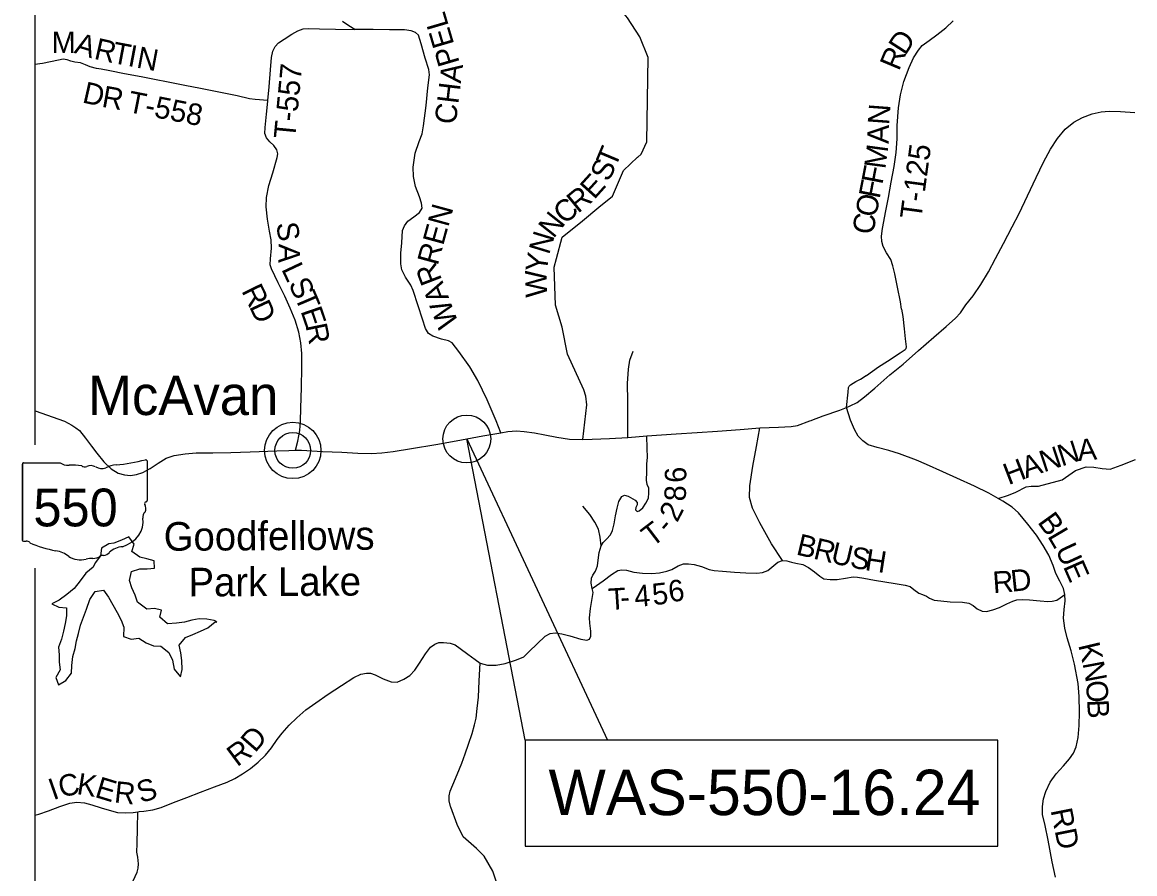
# Model space of a CAD drawing. Extents: x -84548 to 2262448, y -162180 to 525962.
# Drawn here: x 76911 to 92440, y 147226 to 159110 of the extents above; entities that cross this region are included whole.
import ezdxf

# ---------------------------------------------------------------- set-up
doc = ezdxf.new("R2010")
doc.units = 0
for name, color, linetype in [('GM_X_Adjacent_County_Text', 7, 'Continuous'), ('GM_X_County', 7, 'Continuous'), ('GM_X_County_Road', 7, 'Continuous'), ('GM_X_Interchange_Ramps', 7, 'Continuous'), ('GM_X_Major_Lake_Text', 7, 'Continuous'), ('GM_X_Major_River', 7, 'Continuous'), ('GM_X_Minor_Lake', 7, 'Continuous'), ('GM_X_Minor_River_Text', 7, 'Continuous'), ('GM_X_Rail_Line', 7, 'Continuous'), ('GM_X_Section', 7, 'Continuous'), ('GM_X_Township_Road', 7, 'Continuous'), ('GM_X_Township_Road_Text', 7, 'Continuous'), ('GM_X_Township_ROW', 7, 'Continuous'), ('GM_X_Unincorporated_Text', 7, 'Continuous')]:
    doc.layers.add(name, color=color, linetype=linetype)

msp = doc.modelspace()

# ---------------------------------------------------------------- linework, layer by layer
at = {"layer": 'GM_X_Adjacent_County_Text'}
msp.add_circle((83116, 153294), 334, dxfattribs=at)
at = {"layer": 'GM_X_County'}
for p, q in [((77085, 170686), (77085, 153214)), ((77085, 151493), (77085, 134782))]:
    msp.add_line(p, q, dxfattribs=at)
at = {"layer": 'GM_X_Interchange_Ramps'}
for points in [[(79613, 150749), (79589, 150761), (79487, 150779), (79382, 150783), (79276, 150765), (79175, 150735), (79065, 150723), (78938, 150713), (78831, 150805), (78855, 150906), (78755, 150926), (78650, 150920), (78520, 151014), (78488, 151114), (78441, 151216), (78407, 151317), (78437, 151445), (78552, 151483), (78656, 151483), (78757, 151489), (78751, 151591), (78650, 151619), (78550, 151643), (78439, 151724), (78473, 151826), (78399, 151926), (78294, 151882), (78190, 151842)], [(78190, 151842), (78118, 151832), (78017, 151772), (78005, 151665), (77929, 151563)], [(77929, 151563), (77901, 151507), (77800, 151421), (77720, 151313), (77637, 151208), (77533, 151124), (77428, 151046), (77322, 150992), (77422, 150946), (77527, 150938), (77529, 150827), (77511, 150717), (77488, 150613), (77460, 150499), (77416, 150388), (77426, 150282), (77424, 150178), (77442, 150074), (77378, 149963), (77416, 149861), (77517, 149925), (77597, 150026), (77601, 150130), (77615, 150258), (77649, 150370), (77669, 150477), (77696, 150581), (77726, 150697), (77768, 150809), (77806, 150920), (77854, 151052), (77929, 151164), (78047, 151184), (78114, 151084), (78174, 150978), (78236, 150874), (78291, 150765), (78331, 150665), (78325, 150535), (78429, 150499), (78538, 150515), (78640, 150449), (78741, 150409), (78847, 150403), (78956, 150312), (79008, 150206), (79032, 150082), (79119, 149976), (79141, 150076), (79137, 150200), (79123, 150308), (79101, 150417), (79189, 150523), (79290, 150565), (79398, 150611), (79499, 150657), (79605, 150741)], [(79605, 150741), (79629, 150737)], [(79629, 150737), (79613, 150749)]]:
    msp.add_lwpolyline(points, dxfattribs=at)
at = {"layer": 'GM_X_Major_Lake_Text'}
for points in [[(88418, 153735), (88468, 153756), (88567, 153804), (88669, 153883), (88810, 154002), (89021, 154188), (89205, 154337), (89422, 154529), (89633, 154715), (89806, 154862), (89937, 154981), (90006, 155055), (90083, 155166), (90183, 155293), (90293, 155450), (90398, 155629), (90495, 155812), (90610, 156023), (90730, 156254), (90825, 156443), (90945, 156688), (91065, 156943), (91164, 157158), (91263, 157341), (91360, 157488), (91467, 157617), (91588, 157716), (91709, 157783), (91845, 157832), (91971, 157861), (92085, 157869), (92241, 157866), (92441, 157852)], [(77085, 153691), (77093, 153688), (77501, 153542), (77602, 153487), (77658, 153449), (77712, 153411), (77795, 153303)], [(87925, 153553), (87930, 153555), (88089, 153617), (88324, 153697), (88418, 153735)], [(80465, 153129), (80633, 153135), (80724, 153137), (80807, 153138), (81101, 153120), (81371, 153108), (81593, 153097), (81787, 153092), (81931, 153099), (82090, 153118), (82346, 153160), (82685, 153216), (82969, 153266), (83342, 153337), (83592, 153380), (83691, 153397), (83811, 153406), (83917, 153398), (84059, 153379), (84207, 153352), (84373, 153319), (84549, 153292), (84737, 153288), (84865, 153292), (85107, 153300), (85365, 153316), (85628, 153338), (86038, 153366), (86332, 153383), (86615, 153405), (86931, 153427), (87207, 153448), (87468, 153461), (87644, 153466), (87732, 153480), (87905, 153546), (87925, 153553)], [(77795, 153303), (77879, 153192), (77953, 153098), (78050, 152976), (78153, 152879), (78249, 152819), (78337, 152792), (78423, 152786), (78505, 152797), (78595, 152826), (78694, 152882), (78808, 152955), (78919, 153026), (79031, 153063), (79185, 153086), (79340, 153099), (79572, 153102), (79822, 153106), (80090, 153116), (80465, 153129)]]:
    msp.add_lwpolyline(points, dxfattribs=at)
at = {"layer": 'GM_X_Major_River'}
for radius in [393, 249]:
    msp.add_circle((80687, 153134), radius, dxfattribs=at)
at = {"layer": 'GM_X_Minor_Lake'}
for points in [[(85502, 157226), (85551, 157270), (85627, 157441), (85646, 158620), (85531, 158905), (85360, 159171), (85265, 159285), (85208, 159343), (85170, 159419), (85208, 159514), (85170, 159666), (85056, 159856), (85075, 160521), (85126, 161488), (85126, 161489)], [(80437, 158763), (80441, 158771), (80488, 158824), (80565, 158874), (80672, 158942), (80759, 158992), (80834, 159017), (80904, 159023), (81062, 159020), (81284, 159016), (81552, 159010)], [(89187, 155106), (89186, 155107), (89168, 155210), (89127, 155413), (89092, 155597), (89063, 155711), (89035, 155797), (88976, 155891), (88926, 155981), (88909, 156049), (88903, 156123), (88918, 156233), (88965, 156476), (89002, 156666), (89039, 156877), (89082, 157097), (89109, 157294), (89122, 157484), (89125, 157671), (89141, 157917), (89170, 158097), (89215, 158282), (89290, 158481), (89352, 158615), (89419, 158720), (89473, 158788), (89568, 158857), (89678, 158935), (89801, 159032), (89905, 159131)], [(80724, 153137), (80758, 153262), (80785, 153413), (80796, 153544), (80800, 153726), (80808, 154013), (80815, 154293), (80813, 154489), (80800, 154637), (80773, 154783), (80721, 154952), (80652, 155121), (80576, 155288), (80485, 155471), (80391, 155667), (80370, 155723), (80378, 155807), (80391, 155955), (80384, 156074), (80362, 156195), (80335, 156361), (80315, 156535), (80318, 156663), (80355, 156830), (80407, 157009), (80471, 157223), (80478, 157275), (80463, 157331), (80423, 157392), (80368, 157443), (80319, 157498), (80298, 157558), (80300, 157640), (80321, 157829), (80339, 158010), (80340, 158019), (80357, 158208), (80378, 158445), (80392, 158618), (80409, 158706), (80437, 158762), (80437, 158763)], [(78010, 158455), (77980, 158460), (77945, 158467), (77860, 158489), (77794, 158518), (77723, 158542), (77643, 158551), (77589, 158568), (77536, 158587), (77484, 158596), (77415, 158580), (77192, 158534), (77085, 158520)], [(80340, 158019), (80163, 158032), (80084, 158043), (79912, 158081), (79633, 158138), (79398, 158185), (79181, 158229), (78948, 158276), (78757, 158313), (78569, 158349), (78340, 158392), (78133, 158432), (78010, 158455)], [(84367, 155812), (84367, 155814), (84448, 156111), (84733, 156339), (84961, 156529), (85151, 156681), (85208, 156814), (85303, 157042), (85501, 157225), (85502, 157226)], [(84737, 153288), (84790, 153772), (84778, 153892), (84752, 153982), (84524, 154476), (84448, 154856), (84353, 155160), (84334, 155693), (84367, 155812)], [(88695, 154182), (88865, 154300), (88990, 154378), (89165, 154497), (89233, 154544), (89249, 154559), (89253, 154578), (89242, 154690), (89226, 154832), (89205, 155004), (89187, 155106)], [(88418, 153735), (88441, 153945), (88446, 154011), (88455, 154032), (88470, 154049), (88546, 154098), (88612, 154130), (88693, 154181), (88695, 154182)], [(84868, 151209), (84850, 151281), (84859, 151351), (84876, 151393), (84913, 151448), (84941, 151523), (84952, 151601), (84966, 151710), (84991, 151801), (85019, 151851), (85068, 151894), (85122, 151955), (85151, 152018), (85173, 152110), (85193, 152219), (85213, 152330), (85237, 152420), (85279, 152489), (85317, 152510), (85367, 152497), (85466, 152441), (85493, 152407), (85494, 152377), (85474, 152339), (85473, 152303), (85492, 152283), (85523, 152290), (85573, 152333), (85617, 152396), (85652, 152470), (85658, 152541), (85657, 152607), (85636, 152660), (85625, 152718), (85628, 152833), (85630, 152943), (85640, 153039), (85636, 153161), (85628, 153338)], [(90535, 152462), (90679, 152508), (90782, 152550), (90925, 152625), (90993, 152637), (91097, 152633), (91426, 152724), (91614, 152854), (91763, 152904), (91867, 152900), (91984, 152884), (92096, 152871), (92251, 152930), (92452, 153008)], [(84991, 151801), (84977, 151924), (84955, 152034), (84905, 152133), (84835, 152240), (84734, 152356)], [(84869, 151209), (84881, 151218), (85018, 151316), (85136, 151402), (85223, 151456), (85278, 151467), (85346, 151461), (85447, 151435), (85567, 151419), (85701, 151414), (85805, 151424), (85908, 151448), (85980, 151473), (86065, 151523), (86140, 151551), (86210, 151552), (86292, 151542), (86393, 151512), (86500, 151472), (86568, 151457), (86684, 151447), (86852, 151437), (87012, 151424), (87164, 151419), (87244, 151432), (87318, 151456), (87375, 151505), (87457, 151575), (87521, 151596), (87529, 151598), (87583, 151595), (87647, 151573), (87707, 151560), (87808, 151540), (87888, 151499), (87968, 151441), (88043, 151378), (88102, 151343), (88186, 151331), (88286, 151333), (88401, 151351), (88511, 151370), (88569, 151367), (88659, 151351), (88808, 151325), (89096, 151279), (89233, 151254), (89305, 151233), (89358, 151192), (89425, 151144), (89475, 151121), (89532, 151100), (89576, 151072), (89639, 151046), (89731, 151037), (89865, 151022), (90035, 151016), (90126, 151003), (90184, 150972), (90239, 150921), (90310, 150889), (90372, 150884), (90461, 150908), (90553, 150942), (90652, 150992), (90739, 151032), (90794, 151049), (90868, 151054), (90972, 151050), (91120, 151035), (91225, 151027), (91289, 151029), (91354, 151044), (91400, 151075), (91466, 151124)], [(77085, 148043), (77142, 148056), (77275, 148102), (77436, 148164), (77573, 148213), (77672, 148227), (77779, 148215), (77883, 148189), (78014, 148145), (78157, 148104), (78239, 148082), (78351, 148076), (78459, 148082), (78524, 148090), (78543, 148093), (78607, 148101), (78734, 148120), (78849, 148150), (79024, 148220), (79210, 148289), (79401, 148365), (79595, 148437), (79770, 148503), (79879, 148553), (79985, 148619), (80096, 148696), (80202, 148784), (80306, 148880), (80388, 148984), (80469, 149098), (80539, 149189), (80637, 149298), (80745, 149400), (80867, 149513), (81008, 149611), (81182, 149733), (81369, 149855), (81539, 149967), (81638, 150013), (81714, 150026), (81774, 150025), (81838, 150001), (81947, 149947), (82062, 149905), (82146, 149901), (82239, 149941), (82320, 149994), (82390, 150068), (82458, 150167), (82538, 150297), (82608, 150387), (82669, 150430), (82726, 150451), (82790, 150452), (82885, 150442), (82953, 150422), (83024, 150371), (83130, 150291), (83233, 150215), (83304, 150166), (83403, 150138), (83528, 150136), (83652, 150159), (83809, 150210), (83910, 150254), (83986, 150326), (84098, 150436), (84210, 150541), (84279, 150578), (84349, 150590), (84441, 150575), (84556, 150544), (84706, 150500), (84791, 150488), (84828, 150499), (84848, 150541), (84846, 150611), (84832, 150723), (84828, 150799), (84842, 150926), (84867, 151069), (84879, 151151), (84868, 151209), (84869, 151209)], [(82888, 148166), (82868, 148244), (82870, 148314), (82883, 148377), (82919, 148466), (82980, 148613), (83047, 148767), (83092, 148898), (83141, 149035), (83190, 149182), (83224, 149303), (83246, 149396), (83263, 149530), (83280, 149691), (83289, 149917), (83304, 150166)], [(83578, 146968), (83480, 147262), (83360, 147469), (83251, 147577), (83067, 147740), (82980, 147914), (82891, 148155), (82888, 148166)], [(78461, 147125), (78514, 147246), (78531, 147302), (78534, 147366), (78522, 147458), (78512, 147528), (78516, 147646), (78521, 147859), (78524, 148090)]]:
    msp.add_lwpolyline(points, dxfattribs=at)
at = {"layer": 'GM_X_Minor_River_Text'}
for points in [[(82197, 155886), (82207, 156033), (82220, 156204), (82246, 156270), (82294, 156332), (82377, 156395), (82457, 156457), (82493, 156517), (82486, 156585), (82458, 156674), (82401, 156816), (82372, 156956), (82368, 157090), (82397, 157284), (82450, 157445), (82495, 157555), (82513, 157663), (82547, 157948), (82574, 158193), (82597, 158375), (82584, 158449), (82536, 158611), (82479, 158811), (82444, 158929), (82398, 158969), (82338, 158991), (82248, 159005), (82038, 159006), (81810, 159009), (81552, 159010), (81470, 159059), (81382, 159121)], [(83592, 153380), (83524, 153547), (83402, 153839), (83269, 154109), (83158, 154302), (83005, 154516), (82914, 154638), (82860, 154666), (82764, 154689), (82644, 154727), (82580, 154767), (82540, 154835), (82499, 154967), (82438, 155151), (82367, 155367), (82334, 155439), (82262, 155551), (82211, 155657), (82193, 155739), (82196, 155871), (82197, 155886), (82197, 155886)], [(91335, 147180), (91286, 147394), (91232, 147695), (91191, 147901), (91152, 148053), (91150, 148163), (91165, 148269), (91197, 148374), (91258, 148504), (91341, 148619), (91445, 148733), (91530, 148828), (91586, 148910), (91623, 148995), (91650, 149129), (91665, 149297), (91670, 149482), (91663, 149698), (91650, 149880), (91597, 150151), (91552, 150337), (91495, 150517), (91462, 150655), (91446, 150793), (91455, 150915), (91470, 151034), (91466, 151124), (91445, 151208), (91393, 151308), (91338, 151414), (91300, 151530), (91239, 151672), (91162, 151807), (91070, 151953), (90947, 152107), (90818, 152261), (90728, 152340), (90600, 152424), (90535, 152462), (90401, 152539), (90203, 152633), (89958, 152746), (89760, 152833), (89535, 152938), (89391, 153000), (89155, 153085), (89005, 153134), (88845, 153173), (88720, 153213), (88642, 153267), (88578, 153331), (88527, 153426), (88473, 153556), (88418, 153735)]]:
    msp.add_lwpolyline(points, dxfattribs=at)
at = {"layer": 'GM_X_Rail_Line'}
for p, q in [((78653, 152987), (78653, 152434)), ((76912, 152942), (76912, 151886)), ((76912, 151886), (76912, 152942)), ((76912, 151886), (76912, 152942)), ((76929, 152960), (77439, 152960)), ((78652, 152434), (78653, 152434))]:
    msp.add_line(p, q, dxfattribs=at)
for centre, major_axis, start_param, end_param in [((78033, 154401), (1845, 0), 4.814394, 5.042369), ((78633, 152989), (19.4, 0), 6.141152, 7.989035), ((76932, 152945), (20.2, 0), 1.712693, 3.28349), ((77560, 153083), (196, 0), 4.042523, 4.731795), ((77625, 152367), (702, 0), 1.404758, 1.657858), ((77785, 152950), (56.4, 0), 3.836095, 5.185415), ((77867, 152828), (117, 0), 0.950623, 2.079405), ((78019, 152995), (141, 0), 4.081561, 5.145723), ((78268, 152638), (371, 0), 1.699011, 2.107814), ((78648, 152393), (30, 0), 1.883978, 3.671073), ((78457, 152323), (180, 0), 5.934695, 6.695948), ((78632, 152432), (20.7, 0), 5.05454, 6.418171), ((78136, 152132), (462, 0), 5.101752, 6.440018), ((78722, 152203), (131, 0), 2.387724, 3.262537), ((76932, 151883), (20.3, 0), 3.00124, 4.508301), ((76936, 151991), (155, 0), 4.665946, 4.897461), ((76967, 151825), (56, 0), 0.519207, 1.627899), ((77674, 152774), (1333, 0), 4.195997, 4.488961), ((77277, 151411), (417, 0), 0.823519, 1.323587), ((78331, 151589), (253, 0), 1.647645, 2.488434), ((77728, 151819), (265, 0), 4.026481, 4.996735), ((77880, 151454), (217, 0), 1.495662, 1.94098), ((77900, 151740), (141, 0), 4.691044, 5.507374), ((78027, 151638), (39.7, 0), 1.147584, 2.315152), ((78010, 151783), (149, 0), 4.937069, 5.64225)]:
    msp.add_ellipse(centre, major_axis=major_axis, ratio=0.8, start_param=start_param, end_param=end_param, dxfattribs=at)
at = {"layer": 'GM_X_Section'}
for points in [[(83930, 149088), (83116, 153294), (85082, 149088)], [(83930, 147609), (90530, 147609), (90530, 149088), (83930, 149088)]]:
    msp.add_lwpolyline(points, close=True, dxfattribs=at)
at = {"layer": 'GM_X_Township_Road_Text'}
msp.add_lwpolyline([(87521, 151596), (87367, 151832), (87208, 152122), (87104, 152326), (87062, 152477), (87068, 152641), (87108, 152916), (87161, 153188), (87207, 153448)], dxfattribs=at)
at = {"layer": 'GM_X_Township_ROW'}
msp.add_lwpolyline([(85365, 153316), (85365, 153587), (85366, 153823), (85361, 154069), (85375, 154268), (85390, 154394), (85440, 154520)], dxfattribs=at)

# ---------------------------------------------------------------- texts
at = {"layer": 'GM_X_Adjacent_County_Text'}
msp.add_text('McAvan', height=550, rotation=0, dxfattribs=at).set_placement((77829, 153628))
at = {"layer": 'GM_X_County'}
msp.add_text('WAS-550-16.24', height=633.6, dxfattribs=at).set_placement((84257, 148044))
at = {"layer": 'GM_X_County_Road'}
for s, rotation, p in [('PEL', 106.3899, (83018, 158547)), ('CHA', 83.0464, (82962, 157675)), ('REN', 74.6808, (82709, 155704)), ('WAR', 110.9772, (83006, 154908)), ('B', 305.7602, (91074, 152133)), ('L', 300.5231, (91214, 151939)), ('U', 294.8103, (91325, 151753)), ('E', 293.7149, (91435, 151515)), ('K', 283.3922, (91649, 150418)), ('N', 280.6098, (91709, 150165)), ('O', 274.2624, (91756, 149915)), ('B', 272.155, (91776, 149654)), ('RD', 281.3097, (91264, 148113))]:
    msp.add_text(s, height=300, rotation=rotation, dxfattribs=at).set_placement(p)
at = {"layer": 'GM_X_Rail_Line'}
msp.add_text('550', height=528, dxfattribs=at).set_placement((77066, 152074))
at = {"layer": 'GM_X_Township_Road'}
for s, rotation, p in [('M', 0.2333, (77322, 158680)), ('A', 342.9532, (77624, 158685)), ('R', 347.4548, (77901, 158601)), ('D', 57.1798, (89236, 158635)), ('T', 349.2826, (78152, 158545)), ('I', 349.2672, (78373, 158503)), ('N', 349.2655, (78494, 158480)), ('R', 67.186, (89147, 158420)), ('T-557', 84.5229, (80719, 157474)), ('D', 347.2175, (77737, 157993)), ('R', 349.8245, (78009, 157932)), ('T-558', 348.8534, (78368, 157861)), ('N', 85.7668, (89010, 157671)), ('A', 88.6056, (89004, 157411)), ('T', 67.2184, (85189, 157067)), ('M', 82.3671, (88958, 157053)), ('T-125', 82.3666, (89459, 156351)), ('S', 64.5291, (85096, 156871)), ('E', 47.9617, (84893, 156626)), ('F', 79.1899, (88917, 156836)), ('F', 79.0381, (88878, 156637)), ('R', 39.4593, (84668, 156435)), ('O', 79.1305, (88829, 156378)), ('C', 39.7836, (84479, 156278)), ('N', 51.6736, (84327, 156083)), ('C', 81.6337, (88793, 156137)), ('S', 277.8647, (80456, 156303)), ('N', 73.0783, (84263, 155856)), ('A', 268.5792, (80490, 156019)), ('L', 295.2472, (80523, 155666)), ('Y', 82.0479, (84230, 155607)), ('W', 91.555, (84240, 155273)), ('R', 296.1112, (79966, 155363)), ('S', 295.7986, (80620, 155460)), ('T', 293.0104, (80707, 155281)), ('D', 294.9431, (80074, 155143)), ('E', 288.9743, (80792, 155080)), ('R', 281.561, (80863, 154878)), ('N', 17.863, (91419, 152909)), ('A', 5.0244, (91653, 152986)), ('N', 18.3295, (91169, 152826)), ('H', 21.0323, (90677, 152647)), ('A', 18.8197, (90920, 152741)), ('6', 91.8381, (86184, 152687)), ('8', 88.3779, (86172, 152421)), ('2', 63.2385, (86054, 152118)), ('T', 37.3053, (85701, 151775)), ('-', 49.436, (85930, 151959)), ('B', 346.4579, (87701, 151684)), ('R', 346.456, (87941, 151626)), ('U', 346.8998, (88183, 151568)), ('S', 349.1221, (88452, 151506)), ('H', 351.1425, (88663, 151466)), ('R', 4.127, (90467, 151142)), ('D', 6.1461, (90724, 151161)), ('4', 4.5891, (85465, 150948)), ('5', 6.2983, (85719, 150973)), ('6', 7.4922, (85948, 151014)), ('T', 3.6667, (85102, 150906)), ('-', 3.8952, (85266, 150933)), ('D', 48.9937, (80160, 148905)), ('R', 36.4655, (79910, 148710)), ('C', 12.0991, (77449, 148288)), ('K', 350.9191, (77661, 148339)), ('I', 19.3088, (77342, 148250)), ('E', 342.9408, (77911, 148300)), ('R', 353.8481, (78186, 148222)), ('S', 17.5896, (78565, 148209))]:
    msp.add_text(s, height=300, rotation=rotation, dxfattribs=at).set_placement(p)
at = {"layer": 'GM_X_Unincorporated_Text'}
for s, p in [('Goodfellows', (78886, 151733)), ('Park Lake', (79232, 151095))]:
    msp.add_text(s, height=400, rotation=0.3165, dxfattribs=at).set_placement(p)

doc.saveas('drawing.dxf')
